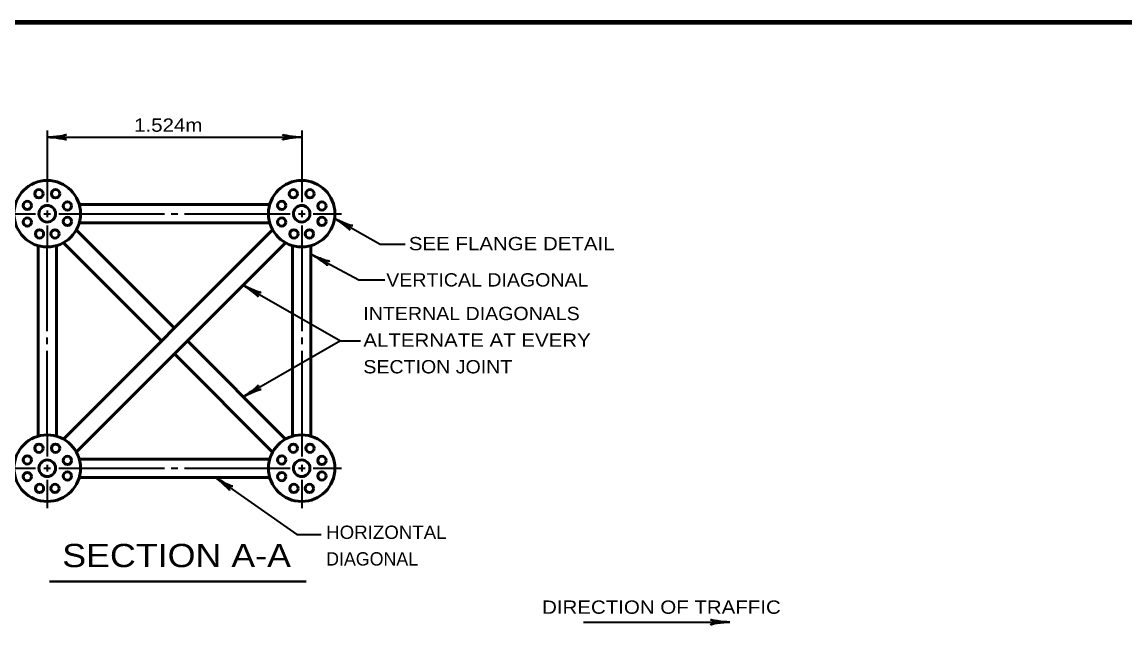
# Model space of a CAD drawing. Extents: x -35 to 821, y -13 to 531.
# Drawn here: x 455.8 to 654.8, y 416 to 525.1 of the extents above; entities that cross this region are included whole.
import ezdxf

# ---------------------------------------------------------------- set-up
doc = ezdxf.new("R2010")
doc.units = 0
doc.header["$LTSCALE"] = 0.96
doc.layers.add('1', color=7, linetype='Continuous', lineweight=53)

msp = doc.modelspace()

# ---------------------------------------------------------------- linework, layer by layer
at = {"layer": '1', "lineweight": 35}
for p, q in [((460.3808, 505.5163), (460.3808, 492.6163)), ((506.2808, 505.5163), (506.2808, 492.6163)), ((460.3808, 504.3163), (506.2808, 504.3163)), ((447.1808, 490.5163), (458.2808, 490.5163)), ((459.7808, 490.5163), (460.9808, 490.5163)), ((460.3808, 491.1163), (460.3808, 489.9163)), ((462.4808, 490.5163), (466.3808, 490.5163)), ((466.3808, 490.5163), (481.5308, 490.5163)), ((482.7308, 490.5163), (483.9308, 490.5163)), ((485.1308, 490.5163), (500.2808, 490.5163)), ((500.2808, 490.5163), (504.1808, 490.5163)), ((505.6808, 490.5163), (506.8808, 490.5163)), ((506.2808, 491.1163), (506.2808, 489.9163)), ((508.3808, 490.5163), (513.4808, 490.5163)), ((460.3808, 488.4163), (460.3808, 484.5163)), ((506.2808, 488.4163), (506.2808, 484.5163)), ((460.3808, 469.3663), (460.3808, 484.5163)), ((506.2808, 484.5163), (506.2808, 469.3663)), ((460.3808, 466.9663), (460.3808, 468.1663)), ((506.2808, 468.1663), (506.2808, 466.9663)), ((460.3808, 450.6163), (460.3808, 465.7663)), ((506.2808, 465.7663), (506.2808, 450.6163)), ((513.2643, 467.5663), (516.8643, 467.5663)), ((460.3808, 450.6163), (460.3808, 446.7163)), ((506.2808, 450.6163), (506.2808, 446.7163)), ((447.1808, 444.6163), (458.2808, 444.6163)), ((459.7808, 444.6163), (460.9808, 444.6163)), ((460.3808, 445.2163), (460.3808, 444.0163)), ((462.4808, 444.6163), (466.3808, 444.6163)), ((466.3808, 444.6163), (481.5308, 444.6163)), ((482.7308, 444.6163), (483.9308, 444.6163)), ((485.1308, 444.6163), (500.2808, 444.6163)), ((500.2808, 444.6163), (504.1808, 444.6163)), ((505.6808, 444.6163), (506.8808, 444.6163)), ((506.2808, 445.2163), (506.2808, 444.0163)), ((508.3808, 444.6163), (513.4808, 444.6163)), ((460.3808, 442.5163), (460.3808, 437.4163)), ((506.2808, 442.5163), (506.2808, 437.4163)), ((557.1048, 416.8595), (583.5048, 416.8595))]:
    msp.add_line(p, q, dxfattribs=at)
at = {"layer": '1'}
for p, q in [((500.5121, 492.1663), (466.1495, 492.1663)), ((501.035, 487.604), (463.2931, 449.8621)), ((465.6266, 487.6039), (483.3308, 469.8998)), ((500.5121, 488.8663), (466.1495, 488.8663)), ((458.7308, 484.7476), (458.7308, 450.385)), ((462.0308, 484.7476), (462.0308, 450.385)), ((463.293, 485.2705), (480.9973, 467.5663)), ((503.3685, 485.2705), (465.6266, 447.5286)), ((504.6308, 450.385), (504.6308, 484.7476)), ((507.9308, 450.385), (507.9308, 484.7476)), ((485.6643, 467.5663), (503.3684, 449.862)), ((483.3308, 465.2328), (501.035, 447.5285)), ((466.1495, 446.2663), (500.5121, 446.2663)), ((466.1495, 442.9663), (500.5121, 442.9663))]:
    msp.add_line(p, q, dxfattribs=at)
at = {"layer": '1', "lineweight": 40}
msp.add_line((460.8067, 424.2147), (507.0886, 424.2147), dxfattribs=at)
at = {"layer": '1', "lineweight": 158}
msp.add_lwpolyline([(814.3112, 525.0846), (22.6112, 524.9846), (22.7112, -1.0154)], dxfattribs=at)
at = {"layer": '1', "lineweight": 35}
for points in [[(512.2547, 489.6495), (520.4266, 485.0173), (524.929, 485.0173)], [(508.0772, 483.1765), (516.6202, 478.6188), (521.259, 478.6188)], [(495.7317, 477.6337), (513.2643, 467.5663), (495.7317, 457.4988)], [(490.7298, 442.9663), (505.4224, 432.6499), (509.7884, 432.6499)]]:
    msp.add_lwpolyline(points, dxfattribs=at)
at = {"layer": '1'}
for centre, radius in [((460.3808, 490.5163), 6), ((506.2808, 490.5163), 6), ((458.8808, 494.1163), 0.75), ((461.8808, 494.1163), 0.75), ((504.7808, 494.1163), 0.75), ((507.7808, 494.1163), 0.75), ((456.7808, 492.0163), 0.75), ((460.3808, 490.5163), 1.5), ((464.0222, 491.9128), 0.75), ((502.6808, 492.0163), 0.75), ((506.2808, 490.5163), 1.5), ((509.9222, 491.9128), 0.75), ((456.7808, 489.0163), 0.75), ((464.0222, 489.1197), 0.75), ((502.6808, 489.0163), 0.75), ((509.9222, 489.1197), 0.75), ((458.9842, 486.8749), 0.75), ((461.7774, 486.8749), 0.75), ((504.8842, 486.8749), 0.75), ((507.6774, 486.8749), 0.75), ((460.3808, 444.6163), 6), ((506.2808, 444.6163), 6), ((458.8808, 448.2163), 0.75), ((461.8808, 448.2163), 0.75), ((504.7808, 448.2163), 0.75), ((507.7808, 448.2163), 0.75), ((456.7808, 446.1163), 0.75), ((460.3808, 444.6163), 1.5), ((464.0222, 446.0128), 0.75), ((502.6808, 446.1163), 0.75), ((506.2808, 444.6163), 1.5), ((509.9222, 446.0128), 0.75), ((456.7808, 443.1163), 0.75), ((464.0222, 443.2197), 0.75), ((502.6808, 443.1163), 0.75), ((509.9222, 443.2197), 0.75), ((458.9842, 440.9749), 0.75), ((461.7774, 440.9749), 0.75), ((504.8842, 440.9749), 0.75), ((507.6774, 440.9749), 0.75)]:
    msp.add_circle(centre, radius, dxfattribs=at)
at = {"layer": '1', "lineweight": 40}
for centre, major_axis, ratio, start_param, end_param in [((461.7254, 504.0624), (-2.1077, 0.2108), 0.07063, 3.14071475, 5.41810995), ((461.7254, 504.0624), (-2.1077, 0.2108), 0.07063, 3.14071475, 5.41810995), ((461.6902, 504.6479), (-2.1428, -0.1874), 0.122415, 0.89635335, 3.14159265), ((461.6902, 504.6479), (-2.1428, -0.1874), 0.122415, 0.89635335, 3.14159265), ((504.9714, 503.9847), (2.1428, 0.1874), 0.122415, 0.89635335, 3.14159265), ((504.9714, 503.9847), (2.1428, 0.1874), 0.122415, 0.89635335, 3.14159265), ((504.9362, 504.5702), (2.1077, -0.2108), 0.07063, 3.14071475, 5.41810995), ((504.9362, 504.5702), (2.1077, -0.2108), 0.07063, 3.14071475, 5.41810995), ((513.2992, 488.7655), (-1.7297, 1.2228), 0.07063, 3.14071475, 5.41810995), ((513.2992, 488.7655), (-1.7297, 1.2228), 0.07063, 3.14071475, 5.41810995), ((513.5574, 489.2922), (-1.9566, 0.8937), 0.122415, 0.89635335, 3.14159265), ((513.5574, 489.2922), (-1.9566, 0.8937), 0.122415, 0.89635335, 3.14159265), ((509.144, 482.3196), (1.7604, -1.1781), 0.07063, 6.28230741, 8.55970261), ((509.3886, 482.8527), (-1.9788, 0.8433), 0.122415, 0.89635335, 3.14159265), ((496.7713, 476.7439), (1.7229, -1.2324), 0.07063, 6.28230741, 8.55970261), ((497.0324, 477.2692), (-1.9516, 0.9045), 0.122415, 0.89635335, 3.14159265), ((496.7021, 458.4384), (-1.765, -1.2295), 0.122415, 0.89635335, 3.14159265), ((497.0242, 457.9482), (-1.9328, -0.8668), 0.07063, 3.14071475, 5.41810995), ((491.6843, 441.9858), (-1.6039, 1.3837), 0.07063, 3.14071475, 5.41810995), ((491.992, 442.4852), (-1.8614, 1.078), 0.122415, 0.89635335, 3.14159265), ((582.1954, 416.5279), (2.1428, 0.1874), 0.122415, 0.89635335, 3.14159265), ((582.1602, 417.1134), (2.1077, -0.2108), 0.07063, 3.14071475, 5.41810995)]:
    msp.add_ellipse(centre, major_axis=major_axis, ratio=ratio, start_param=start_param, end_param=end_param, dxfattribs=at)

# ---------------------------------------------------------------- texts
at = {"layer": '1'}
for s, height, width, p in [('1.524m', 2.4, 1.15, (476.0548, 505.2988)), ('SEE FLANGE DETAIL', 2.4, 1.15, (525.6112, 483.9254)), ('VERTICAL DIAGONAL', 2.4, 1.1, (521.5319, 477.3904)), ('INTERNAL DIAGONALS', 2.4, 1.1, (517.409, 471.3213)), ('ALTERNATE AT EVERY', 2.4, 1.15, (517.409, 466.5213)), ('SECTION JOINT', 2.4, 1.1, (517.409, 461.7213)), ('HORIZONTAL', 2.4, 1.05, (510.6996, 431.8691)), ('SECTION A-A', 4.2, 1.15, (463.0826, 426.7759)), ('DIRECTION OF TRAFFIC', 2.4, 1.15, (549.6532, 418.3628))]:
    msp.add_text(s, height=height, dxfattribs=dict(at, width=width)).set_placement(p)
msp.add_text('DIAGONAL', height=2.4, dxfattribs=at).set_placement((510.6996, 427.0691))

doc.saveas('drawing.dxf')
